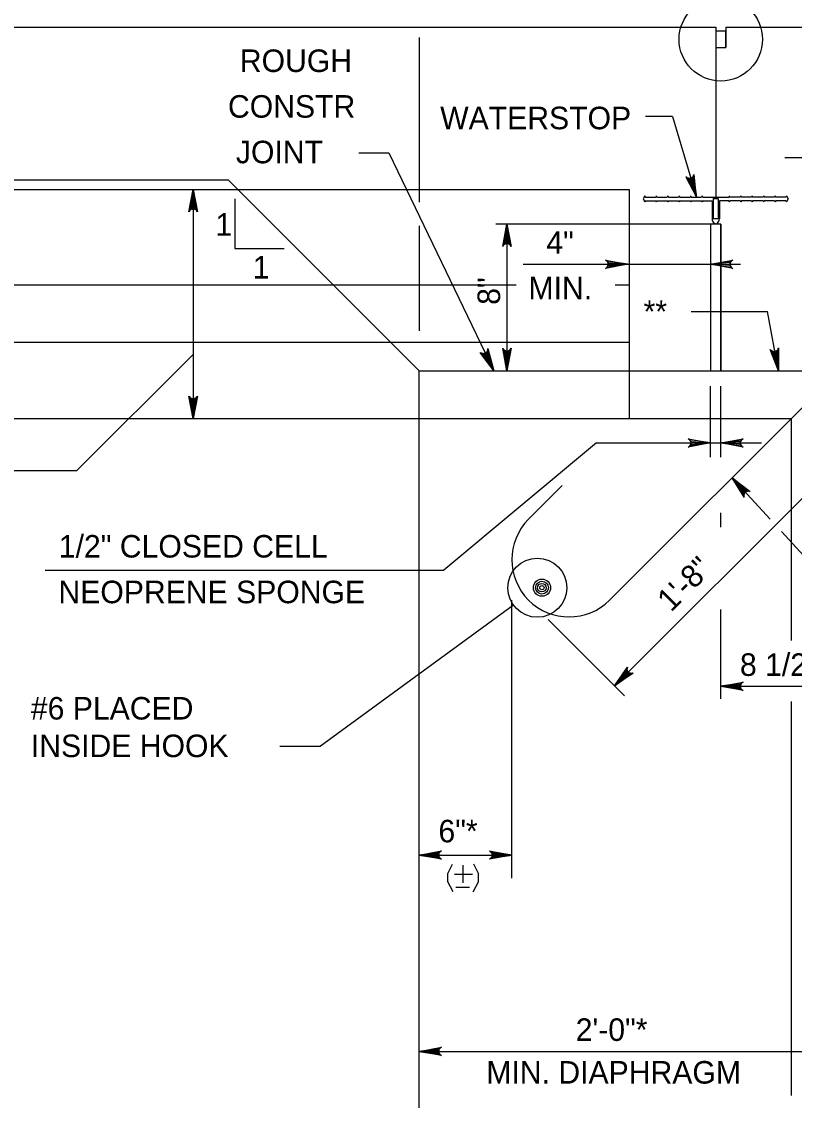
# Model space of a CAD drawing. Extents: x 636530 to 644067, y 294168 to 299122.
# Drawn here: x 639124.7 to 639227.5, y 295723.5 to 295867 of the extents above; entities that cross this region are included whole.
import ezdxf

# ---------------------------------------------------------------- set-up
doc = ezdxf.new("R2010")
doc.units = 0
doc.layers.add('1', color=7, linetype='Continuous')

msp = doc.modelspace()

# ---------------------------------------------------------------- linework, layer by layer
at = {"layer": '1'}
for p, q in [((639115.37, 295866.3), (639217.06, 295866.3)), ((639217.06, 295866.3), (639217.06, 295843.69)), ((639218.41, 295866.3), (639367.07, 295866.3)), ((639218.41, 295866.3), (639218.41, 295863.6)), ((639177.59, 295864.93), (639177.59, 295843.02)), ((639217.06, 295863.6), (639218.41, 295863.6)), ((639202.94, 295790.04), (639267.76, 295854.87)), ((639211.29, 295854.39), (639207.72, 295854.39)), ((639211.29, 295854.39), (639214.49, 295843.69)), ((639169.6, 295849.57), (639173.57, 295849.57)), ((639173.57, 295849.57), (639187.53, 295820.58)), ((639226.27, 295848.95), (639253.17, 295848.95)), ((639115.37, 295845.98), (639152.19, 295845.98)), ((639177.59, 295820.58), (639152.19, 295845.98)), ((639115.37, 295844.71), (639153.46, 295844.71)), ((639147.54, 295844.71), (639147.54, 295814.23)), ((639153.46, 295844.71), (639205.53, 295844.71)), ((639205.53, 295844.71), (639205.53, 295814.23)), ((639207.63, 295843.84), (639207.4, 295843.44)), ((639207.63, 295843.84), (639207.71, 295843.69)), ((639207.71, 295843.69), (639209.07, 295843.69)), ((639209.15, 295843.84), (639209.07, 295843.69)), ((639209.15, 295843.84), (639209.24, 295843.69)), ((639209.24, 295843.69), (639210.59, 295843.69)), ((639210.68, 295843.84), (639210.59, 295843.69)), ((639210.68, 295843.84), (639210.76, 295843.69)), ((639210.76, 295843.69), (639212.12, 295843.69)), ((639212.2, 295843.84), (639212.12, 295843.69)), ((639212.2, 295843.84), (639212.28, 295843.69)), ((639212.28, 295843.69), (639213.64, 295843.69)), ((639213.72, 295843.84), (639213.64, 295843.69)), ((639213.72, 295843.84), (639213.81, 295843.69)), ((639213.81, 295843.69), (639215.16, 295843.69)), ((639215.25, 295843.84), (639215.16, 295843.69)), ((639215.25, 295843.84), (639215.33, 295843.69)), ((639215.33, 295843.69), (639218.78, 295843.69)), ((639218.86, 295843.84), (639218.78, 295843.69)), ((639218.86, 295843.84), (639218.95, 295843.69)), ((639220.3, 295843.69), (639218.95, 295843.69)), ((639220.39, 295843.84), (639220.3, 295843.69)), ((639220.39, 295843.84), (639220.47, 295843.69)), ((639221.83, 295843.69), (639220.47, 295843.69)), ((639221.91, 295843.84), (639221.83, 295843.69)), ((639221.91, 295843.84), (639221.99, 295843.69)), ((639223.35, 295843.69), (639221.99, 295843.69)), ((639223.44, 295843.84), (639223.35, 295843.69)), ((639223.44, 295843.84), (639223.52, 295843.69)), ((639224.88, 295843.69), (639223.52, 295843.69)), ((639224.96, 295843.84), (639224.88, 295843.69)), ((639224.96, 295843.84), (639225.04, 295843.69)), ((639226.4, 295843.69), (639225.04, 295843.69)), ((639226.48, 295843.84), (639226.4, 295843.69)), ((639226.48, 295843.84), (639226.71, 295843.44)), ((639153.07, 295843.43), (639153.07, 295836.85)), ((639207.4, 295843.44), (639207.63, 295843.03)), ((639207.71, 295843.18), (639207.63, 295843.03)), ((639207.71, 295843.18), (639209.07, 295843.18)), ((639209.07, 295843.18), (639209.15, 295843.03)), ((639209.24, 295843.18), (639209.15, 295843.03)), ((639209.24, 295843.18), (639210.59, 295843.18)), ((639210.59, 295843.18), (639210.68, 295843.03)), ((639210.76, 295843.18), (639210.68, 295843.03)), ((639210.76, 295843.18), (639212.12, 295843.18)), ((639212.12, 295843.18), (639212.2, 295843.03)), ((639212.28, 295843.18), (639212.2, 295843.03)), ((639212.28, 295843.18), (639213.64, 295843.18)), ((639213.64, 295843.18), (639213.72, 295843.03)), ((639213.81, 295843.18), (639213.72, 295843.03)), ((639213.81, 295843.18), (639215.16, 295843.18)), ((639215.16, 295843.18), (639215.25, 295843.03)), ((639215.33, 295843.18), (639215.25, 295843.03)), ((639215.33, 295843.18), (639216.57, 295843.18)), ((639216.57, 295843.18), (639216.57, 295840.78)), ((639216.72, 295843.49), (639217.39, 295843.49)), ((639216.72, 295843.49), (639216.72, 295840.78)), ((639217.39, 295843.49), (639217.39, 295840.78)), ((639217.54, 295843.18), (639217.54, 295840.78)), ((639218.78, 295843.18), (639217.54, 295843.18)), ((639218.78, 295843.18), (639218.86, 295843.03)), ((639218.95, 295843.18), (639218.86, 295843.03)), ((639220.3, 295843.18), (639218.95, 295843.18)), ((639220.3, 295843.18), (639220.39, 295843.03)), ((639220.47, 295843.18), (639220.39, 295843.03)), ((639221.83, 295843.18), (639220.47, 295843.18)), ((639221.83, 295843.18), (639221.91, 295843.03)), ((639221.99, 295843.18), (639221.91, 295843.03)), ((639223.35, 295843.18), (639221.99, 295843.18)), ((639223.35, 295843.18), (639223.44, 295843.03)), ((639223.52, 295843.18), (639223.44, 295843.03)), ((639224.88, 295843.18), (639223.52, 295843.18)), ((639224.88, 295843.18), (639224.96, 295843.03)), ((639225.04, 295843.18), (639224.96, 295843.03)), ((639226.4, 295843.18), (639225.04, 295843.18)), ((639226.4, 295843.18), (639226.48, 295843.03)), ((639226.71, 295843.44), (639226.48, 295843.03)), ((639217.39, 295840.78), (639216.72, 295840.78)), ((639177.59, 295839.86), (639177.59, 295825.88)), ((639216.37, 295840.1), (639187.81, 295840.1)), ((639189.28, 295840.1), (639189.28, 295820.58)), ((639216.37, 295840.1), (639216.37, 295820.58)), ((639217.72, 295840.1), (639217.72, 295820.58)), ((639153.07, 295836.85), (639159.65, 295836.85)), ((639191.42, 295834.76), (639220.37, 295834.76)), ((639115.37, 295832.01), (639166.16, 295832.01)), ((639166.16, 295832.01), (639190.5, 295832.01)), ((639203.67, 295832.01), (639205.53, 295832.01)), ((639213.8, 295828.46), (639223.93, 295828.46)), ((639225.42, 295820.58), (639223.93, 295828.46)), ((639115.37, 295824.39), (639173.78, 295824.39)), ((639173.78, 295824.39), (639205.53, 295824.39)), ((639147.54, 295822.74), (639132.07, 295807.3)), ((639177.59, 295717.07), (639177.59, 295820.58)), ((639177.59, 295820.58), (639216.37, 295820.58)), ((639217.72, 295820.58), (639367.07, 295820.58)), ((639216.37, 295809.05), (639216.37, 295818.52)), ((639217.72, 295809.05), (639217.72, 295818.52)), ((639115.37, 295814.23), (639177.59, 295814.23)), ((639177.59, 295814.23), (639227.12, 295814.23)), ((639239.51, 295814.54), (639203.58, 295778.62)), ((639227.12, 295784.68), (639227.12, 295814.23)), ((639201.2, 295810.97), (639180.89, 295794.02)), ((639201.2, 295810.97), (639223.16, 295810.97)), ((639080.4, 295807.3), (639132.07, 295807.3)), ((639224.28, 295800.82), (639219.23, 295806.33)), ((639192.16, 295800.82), (639196.65, 295805.31)), ((639217.72, 295799.76), (639217.72, 295801.65)), ((639250.03, 295772.74), (639225.8, 295799.16)), ((639127.87, 295794.02), (639180.89, 295794.02)), ((639190.15, 295789.37), (639164.48, 295770.59)), ((639189.93, 295753.02), (639189.93, 295790.06)), ((639217.72, 295776.91), (639217.72, 295788.79)), ((639204.92, 295777.29), (639194.76, 295787.45)), ((639217.72, 295778.58), (639238.55, 295778.58)), ((639227.12, 295724.13), (639227.12, 295776.54)), ((639159.05, 295770.59), (639164.48, 295770.59)), ((639177.59, 295756.12), (639189.93, 295756.12)), ((639183.46, 295752.42), (639183.46, 295754.79)), ((639182.3, 295753.58), (639184.71, 295753.58)), ((639182.48, 295751.82), (639184.29, 295751.82)), ((639177.59, 295729.99), (639296.46, 295729.99))]:
    msp.add_line(p, q, dxfattribs=at)
for points in [[(639217.06, 295863.6), (639218.41, 295863.6), (639218.41, 295865.77), (639217.06, 295865.77)], [(639216.37, 295820.58), (639217.72, 295820.58), (639217.72, 295840.1), (639216.37, 295840.1)]]:
    msp.add_lwpolyline(points, close=True, dxfattribs=at)
for points in [[(639214.49, 295843.69), (639214.17, 295846.71), (639214.12, 295846.58), (639214.08, 295846.44), (639214, 295846.36), (639213.92, 295846.27), (639213.83, 295846.23), (639213.74, 295846.18), (639213.64, 295846.17), (639213.54, 295846.16), (639213.43, 295846.19), (639213.31, 295846.21), (639213.21, 295846.3), (639213.1, 295846.39), (639214.49, 295843.69), (639213.21, 295846.3), (639213.31, 295846.21), (639214.49, 295843.69), (639213.43, 295846.19), (639213.54, 295846.16), (639214.49, 295843.69), (639213.64, 295846.17), (639213.74, 295846.18), (639214.49, 295843.69), (639213.83, 295846.23), (639213.92, 295846.27), (639214.49, 295843.69), (639214, 295846.36), (639214.08, 295846.44), (639214.49, 295843.69), (639214.12, 295846.58)], [(639147.54, 295844.71), (639148.1, 295841.73), (639148.02, 295841.84), (639147.94, 295841.96), (639147.84, 295842.01), (639147.74, 295842.07), (639147.64, 295842.09), (639147.54, 295842.11), (639147.44, 295842.09), (639147.34, 295842.07), (639147.24, 295842.01), (639147.14, 295841.96), (639147.06, 295841.84), (639146.98, 295841.73), (639147.54, 295844.71), (639147.06, 295841.84), (639147.14, 295841.96), (639147.54, 295844.71), (639147.24, 295842.01), (639147.34, 295842.07), (639147.54, 295844.71), (639147.44, 295842.09), (639147.54, 295842.11), (639147.54, 295844.71), (639147.64, 295842.09), (639147.74, 295842.07), (639147.54, 295844.71), (639147.84, 295842.01), (639147.94, 295841.96), (639147.54, 295844.71), (639148.02, 295841.84)], [(639189.28, 295840.1), (639189.84, 295837.12), (639189.76, 295837.24), (639189.68, 295837.35), (639189.58, 295837.41), (639189.48, 295837.47), (639189.38, 295837.49), (639189.28, 295837.5), (639189.18, 295837.49), (639189.08, 295837.47), (639188.98, 295837.41), (639188.88, 295837.35), (639188.8, 295837.24), (639188.72, 295837.12), (639189.28, 295840.1), (639188.8, 295837.24), (639188.88, 295837.35), (639189.28, 295840.1), (639188.98, 295837.41), (639189.08, 295837.47), (639189.28, 295840.1), (639189.18, 295837.49), (639189.28, 295837.5), (639189.28, 295840.1), (639189.38, 295837.49), (639189.48, 295837.47), (639189.28, 295840.1), (639189.58, 295837.41), (639189.68, 295837.35), (639189.28, 295840.1), (639189.76, 295837.24)], [(639205.37, 295834.76), (639202.39, 295834.2), (639202.62, 295834.36), (639202.74, 295834.56), (639202.77, 295834.76), (639202.74, 295834.96), (639202.62, 295835.16), (639202.39, 295835.31), (639205.37, 295834.76), (639202.62, 295835.16), (639202.74, 295834.96), (639205.37, 295834.76), (639202.77, 295834.76), (639202.74, 295834.56), (639205.37, 295834.76), (639202.62, 295834.36)], [(639216.37, 295834.76), (639219.35, 295835.31), (639219.12, 295835.16), (639219, 295834.96), (639218.97, 295834.76), (639219, 295834.56), (639219.12, 295834.36), (639219.35, 295834.2), (639216.37, 295834.76), (639219.12, 295834.36), (639219, 295834.56), (639216.37, 295834.76), (639218.97, 295834.76), (639219, 295834.96), (639216.37, 295834.76), (639219.12, 295835.16)], [(639189.28, 295820.58), (639188.72, 295823.56), (639188.8, 295823.45), (639188.88, 295823.33), (639188.98, 295823.27), (639189.08, 295823.21), (639189.18, 295823.19), (639189.28, 295823.18), (639189.38, 295823.19), (639189.48, 295823.21), (639189.58, 295823.27), (639189.68, 295823.33), (639189.76, 295823.45), (639189.84, 295823.56), (639189.28, 295820.58), (639189.76, 295823.45), (639189.68, 295823.33), (639189.28, 295820.58), (639189.58, 295823.27), (639189.48, 295823.21), (639189.28, 295820.58), (639189.38, 295823.19), (639189.28, 295823.18), (639189.28, 295820.58), (639189.18, 295823.19), (639189.08, 295823.21), (639189.28, 295820.58), (639188.98, 295823.27), (639188.88, 295823.33), (639189.28, 295820.58), (639188.8, 295823.45)], [(639225.42, 295820.58), (639224.31, 295823.4), (639224.41, 295823.31), (639224.51, 295823.21), (639224.62, 295823.17), (639224.73, 295823.13), (639224.83, 295823.13), (639224.93, 295823.13), (639225.03, 295823.17), (639225.13, 295823.2), (639225.21, 295823.28), (639225.3, 295823.36), (639225.36, 295823.48), (639225.41, 295823.61), (639225.42, 295820.58), (639225.36, 295823.48), (639225.3, 295823.36), (639225.42, 295820.58), (639225.21, 295823.28), (639225.13, 295823.2), (639225.42, 295820.58), (639225.03, 295823.17), (639224.93, 295823.13), (639225.42, 295820.58), (639224.83, 295823.13), (639224.73, 295823.13), (639225.42, 295820.58), (639224.62, 295823.17), (639224.51, 295823.21), (639225.42, 295820.58), (639224.41, 295823.31)], [(639187.53, 295820.58), (639185.73, 295823.02), (639185.85, 295822.95), (639185.97, 295822.88), (639186.09, 295822.87), (639186.21, 295822.86), (639186.3, 295822.89), (639186.4, 295822.92), (639186.48, 295822.98), (639186.57, 295823.04), (639186.63, 295823.13), (639186.7, 295823.23), (639186.72, 295823.37), (639186.74, 295823.51), (639187.53, 295820.58), (639186.72, 295823.37), (639186.7, 295823.23), (639187.53, 295820.58), (639186.63, 295823.13), (639186.57, 295823.04), (639187.53, 295820.58), (639186.48, 295822.98), (639186.4, 295822.92), (639187.53, 295820.58), (639186.3, 295822.89), (639186.21, 295822.86), (639187.53, 295820.58), (639186.09, 295822.87), (639185.97, 295822.88), (639187.53, 295820.58), (639185.85, 295822.95)], [(639147.54, 295814.23), (639146.98, 295817.21), (639147.06, 295817.1), (639147.14, 295816.98), (639147.24, 295816.92), (639147.34, 295816.86), (639147.44, 295816.85), (639147.54, 295816.83), (639147.64, 295816.85), (639147.74, 295816.86), (639147.84, 295816.92), (639147.94, 295816.98), (639148.02, 295817.1), (639148.1, 295817.21), (639147.54, 295814.23), (639148.02, 295817.1), (639147.94, 295816.98), (639147.54, 295814.23), (639147.84, 295816.92), (639147.74, 295816.86), (639147.54, 295814.23), (639147.64, 295816.85), (639147.54, 295816.83), (639147.54, 295814.23), (639147.44, 295816.85), (639147.34, 295816.86), (639147.54, 295814.23), (639147.24, 295816.92), (639147.14, 295816.98), (639147.54, 295814.23), (639147.06, 295817.1)], [(639216.37, 295810.97), (639213.39, 295810.41), (639213.62, 295810.57), (639213.73, 295810.77), (639213.77, 295810.97), (639213.73, 295811.17), (639213.62, 295811.37), (639213.39, 295811.53), (639216.37, 295810.97), (639213.62, 295811.37), (639213.73, 295811.17), (639216.37, 295810.97), (639213.77, 295810.97), (639213.73, 295810.77), (639216.37, 295810.97), (639213.62, 295810.57)], [(639217.72, 295810.97), (639220.7, 295811.53), (639220.47, 295811.37), (639220.35, 295811.17), (639220.32, 295810.97), (639220.35, 295810.77), (639220.47, 295810.57), (639220.7, 295810.41), (639217.72, 295810.97), (639220.47, 295810.57), (639220.35, 295810.77), (639217.72, 295810.97), (639220.32, 295810.97), (639220.35, 295811.17), (639217.72, 295810.97), (639220.47, 295811.37)], [(639219.23, 295806.33), (639221.66, 295804.51), (639221.52, 295804.54), (639221.38, 295804.57), (639221.27, 295804.55), (639221.16, 295804.52), (639221.07, 295804.47), (639220.99, 295804.41), (639220.92, 295804.33), (639220.86, 295804.25), (639220.83, 295804.14), (639220.79, 295804.03), (639220.81, 295803.89), (639220.83, 295803.75), (639219.23, 295806.33), (639220.81, 295803.89), (639220.79, 295804.03), (639219.23, 295806.33), (639220.83, 295804.14), (639220.86, 295804.25), (639219.23, 295806.33), (639220.92, 295804.33), (639220.99, 295804.41), (639219.23, 295806.33), (639221.07, 295804.47), (639221.16, 295804.52), (639219.23, 295806.33), (639221.27, 295804.55), (639221.38, 295804.57), (639219.23, 295806.33), (639221.52, 295804.54)], [(639203.58, 295778.62), (639205.3, 295781.13), (639205.27, 295780.99), (639205.25, 295780.85), (639205.28, 295780.74), (639205.3, 295780.63), (639205.36, 295780.54), (639205.42, 295780.46), (639205.5, 295780.4), (639205.59, 295780.34), (639205.7, 295780.31), (639205.81, 295780.29), (639205.95, 295780.31), (639206.09, 295780.34), (639203.58, 295778.62), (639205.95, 295780.31), (639205.81, 295780.29), (639203.58, 295778.62), (639205.7, 295780.31), (639205.59, 295780.34), (639203.58, 295778.62), (639205.5, 295780.4), (639205.42, 295780.46), (639203.58, 295778.62), (639205.36, 295780.54), (639205.3, 295780.63), (639203.58, 295778.62), (639205.28, 295780.74), (639205.25, 295780.85), (639203.58, 295778.62), (639205.27, 295780.99)], [(639217.72, 295778.58), (639220.7, 295779.14), (639220.59, 295779.06), (639220.47, 295778.98), (639220.41, 295778.88), (639220.35, 295778.78), (639220.34, 295778.68), (639220.32, 295778.58), (639220.34, 295778.48), (639220.35, 295778.38), (639220.41, 295778.28), (639220.47, 295778.18), (639220.59, 295778.1), (639220.7, 295778.02), (639217.72, 295778.58), (639220.59, 295778.1), (639220.47, 295778.18), (639217.72, 295778.58), (639220.41, 295778.28), (639220.35, 295778.38), (639217.72, 295778.58), (639220.34, 295778.48), (639220.32, 295778.58), (639217.72, 295778.58), (639220.34, 295778.68), (639220.35, 295778.78), (639217.72, 295778.58), (639220.41, 295778.88), (639220.47, 295778.98), (639217.72, 295778.58), (639220.59, 295779.06)], [(639177.59, 295756.12), (639180.57, 295756.67), (639180.46, 295756.6), (639180.34, 295756.52), (639180.28, 295756.42), (639180.22, 295756.32), (639180.21, 295756.22), (639180.19, 295756.12), (639180.21, 295756.02), (639180.22, 295755.92), (639180.28, 295755.82), (639180.34, 295755.72), (639180.46, 295755.64), (639180.57, 295755.56), (639177.59, 295756.12), (639180.46, 295755.64), (639180.34, 295755.72), (639177.59, 295756.12), (639180.28, 295755.82), (639180.22, 295755.92), (639177.59, 295756.12), (639180.21, 295756.02), (639180.19, 295756.12), (639177.59, 295756.12), (639180.21, 295756.22), (639180.22, 295756.32), (639177.59, 295756.12), (639180.28, 295756.42), (639180.34, 295756.52), (639177.59, 295756.12), (639180.46, 295756.6)], [(639189.93, 295756.12), (639186.95, 295755.56), (639187.07, 295755.64), (639187.18, 295755.72), (639187.24, 295755.82), (639187.3, 295755.92), (639187.32, 295756.02), (639187.33, 295756.12), (639187.32, 295756.22), (639187.3, 295756.32), (639187.24, 295756.42), (639187.18, 295756.52), (639187.07, 295756.6), (639186.95, 295756.67), (639189.93, 295756.12), (639187.07, 295756.6), (639187.18, 295756.52), (639189.93, 295756.12), (639187.24, 295756.42), (639187.3, 295756.32), (639189.93, 295756.12), (639187.32, 295756.22), (639187.33, 295756.12), (639189.93, 295756.12), (639187.32, 295756.02), (639187.3, 295755.92), (639189.93, 295756.12), (639187.24, 295755.82), (639187.18, 295755.72), (639189.93, 295756.12), (639187.07, 295755.64)], [(639182.11, 295751.22), (639181.42, 295752.56), (639181.42, 295753.67), (639182.02, 295754.92)], [(639184.8, 295751.22), (639185.5, 295752.56), (639185.5, 295753.67), (639184.89, 295754.92)], [(639177.59, 295729.99), (639180.57, 295730.55), (639180.46, 295730.47), (639180.34, 295730.39), (639180.28, 295730.29), (639180.22, 295730.19), (639180.21, 295730.09), (639180.19, 295729.99), (639180.21, 295729.89), (639180.22, 295729.79), (639180.28, 295729.69), (639180.34, 295729.59), (639180.46, 295729.51), (639180.57, 295729.43), (639177.59, 295729.99), (639180.46, 295729.51), (639180.34, 295729.59), (639177.59, 295729.99), (639180.28, 295729.69), (639180.22, 295729.79), (639177.59, 295729.99), (639180.21, 295729.89), (639180.19, 295729.99), (639177.59, 295729.99), (639180.21, 295730.09), (639180.22, 295730.19), (639177.59, 295729.99), (639180.28, 295730.29), (639180.34, 295730.39), (639177.59, 295729.99), (639180.46, 295730.47)]]:
    msp.add_lwpolyline(points, dxfattribs=at)
for centre, radius in [((639217.73, 295864.68), 5.55), ((639193.32, 295791.69), 3.93), ((639193.94, 295791.7), 1.14), ((639193.94, 295791.7), 0.857), ((639193.94, 295791.7), 0.571), ((639193.94, 295791.7), 0.286)]:
    msp.add_circle(centre, radius, dxfattribs=at)
msp.add_arc((639197.55, 295795.43), 7.62, 135, 315, dxfattribs=at)
msp.add_ellipse((639217.06, 295840.78), major_axis=(0, 0.641), ratio=0.75, start_param=1.570796, end_param=4.712389, dxfattribs=at)

# ---------------------------------------------------------------- texts
for s, rotation, p in [('ROUGH', 360, (639153.75, 295860.33)), ('CONSTR', 360, (639152.17, 295854.25)), (' JOINT', 360, (639152.11, 295848.18)), ('1', 360, (639150.51, 295838.55)), ('4"', 360, (639194.52, 295836.14)), ('1', 360, (639155.46, 295832.84)), ('8"', 90, (639188.37, 295829.35)), ('MIN.', 360, (639192.15, 295830.07)), ('**', 360, (639207.46, 295826.95)), ('1/2" CLOSED CELL', 360, (639129.67, 295795.71)), ('1\'-8"', 45, (639211.11, 295788.35)), ('NEOPRENE SPONGE', 360, (639129.62, 295789.63)), ('#6 PLACED', 360, (639125.95, 295774.15)), ('INSIDE HOOK', 360, (639125.95, 295769.15)), ('6"*', 360, (639180.17, 295757.81)), ('2\'-0"*', 360, (639198.43, 295731.38)), ('MIN. DIAPHRAGM', 360, (639186.54, 295725.7))]:
    msp.add_text(s, height=3, rotation=rotation, dxfattribs=at).set_placement(p)
for s, p in [('WATERSTOP', (639180.4, 295852.71)), ('8 1/2"*', (639220.28, 295779.96))]:
    msp.add_text(s, height=3, dxfattribs=at).set_placement(p)

doc.saveas('drawing.dxf')
